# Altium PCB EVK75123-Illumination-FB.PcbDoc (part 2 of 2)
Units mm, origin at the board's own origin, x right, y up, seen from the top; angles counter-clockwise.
Board outline 80 x 50 mm, 4 copper layers (Top Layer, GND, VCC, Bottom Layer), stack 0.99 mm thick; 109 components, 50 nets, 287 pads, 1161 vias.
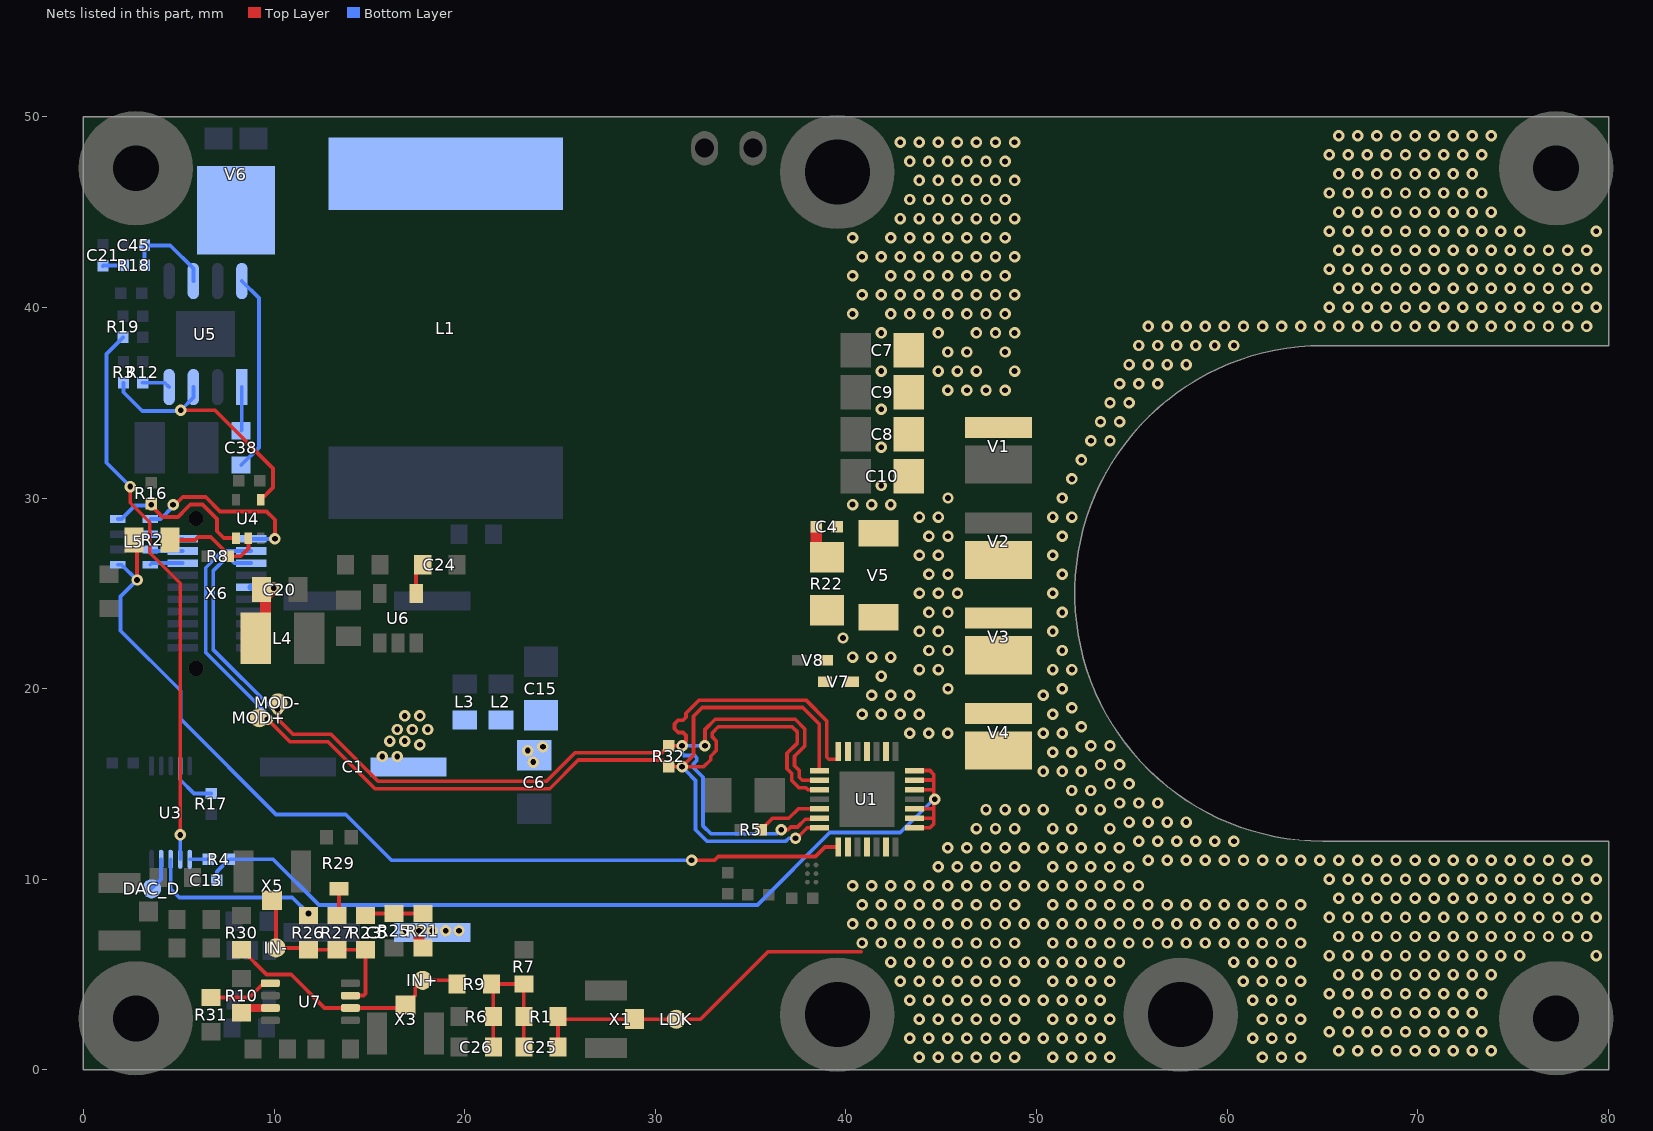
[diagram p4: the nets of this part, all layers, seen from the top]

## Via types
v1: diameter 0.6, hole 0.3, Top Layer to Bottom Layer, tented both sides, 1159 vias
v2: diameter 0.6, hole 0.3, Top Layer to Bottom Layer, 2 vias

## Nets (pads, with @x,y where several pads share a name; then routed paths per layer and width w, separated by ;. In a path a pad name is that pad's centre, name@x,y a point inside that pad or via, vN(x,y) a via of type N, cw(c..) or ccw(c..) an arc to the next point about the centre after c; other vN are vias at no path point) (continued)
LD2: V2.2 V3.1
  other v1: 65.85,1 66.85,1 67.85,1 68.85,1 69.85,1 70.85,1 71.85,1 72.85,1 73.85,1 65.35,2 66.35,2 67.35,2 68.35,2 69.35,2 70.35,2 71.35,2 72.35,2 73.35,2 65.85,3 66.85,3 67.85,3 68.85,3 69.85,3 70.85,3 71.85,3 72.85,3 65.35,4 66.35,4 67.35,4 68.35,4 69.35,4 70.35,4 71.35,4 72.35,4 73.35,4 65.85,5 66.85,5 67.85,5 68.85,5 69.85,5 70.85,5 71.85,5 72.85,5 73.85,5 65.35,6 66.35,6 67.35,6 68.35,6 69.35,6 70.35,6 71.35,6 72.35,6 73.35,6 74.35,6 75.35,6 79.35,6 65.85,7 66.85,7 67.85,7 68.85,7 69.85,7 70.85,7 71.85,7 72.85,7 73.85,7 74.85,7 75.85,7 76.85,7 77.85,7 78.85,7 65.35,8 66.35,8 67.35,8 68.35,8 69.35,8 70.35,8 71.35,8 72.35,8 73.35,8 74.35,8 75.35,8 76.35,8 77.35,8 78.35,8 79.35,8 65.85,9 66.85,9 67.85,9 68.85,9 69.85,9 70.85,9 71.85,9 72.85,9 73.85,9 74.85,9 75.85,9 76.85,9 77.85,9 78.85,9 65.35,10 66.35,10 67.35,10 68.35,10 69.35,10 70.35,10 71.35,10 72.35,10 73.35,10 74.35,10 75.35,10 76.35,10 77.35,10 78.35,10 79.35,10 55.85,11 56.85,11 57.85,11 58.85,11 59.85,11 60.85,11 61.85,11 62.85,11 63.85,11 64.85,11 65.85,11 66.85,11 67.85,11 68.85,11 69.85,11 70.85,11 71.85,11 72.85,11 73.85,11 74.85,11 75.85,11 76.85,11 77.85,11 78.85,11 55.35,12 56.35,12 57.35,12 58.35,12 59.35,12 60.35,12 54.85,13 55.85,13 56.85,13 57.85,13 54.35,14 55.35,14 56.35,14 53.85,15 54.85,15 53.35,16 54.35,16 52.85,17 53.85,17 52.35,18 51.85,19 45.35,20 51.35,20 43.85,21 44.85,21 50.85,21 51.85,21 44.35,22 45.35,22 51.35,22 43.85,23 44.85,23 50.85,23 44.35,24 45.35,24 51.35,24 43.85,25 44.85,25 45.85,25 50.85,25 44.35,26 45.35,26 51.35,26 43.85,27 44.85,27 50.85,27 44.35,28 45.35,28 51.35,28 43.85,29 44.85,29 50.85,29 51.85,29 45.35,30 51.35,30 51.85,31 52.35,32 52.85,33 53.85,33 53.35,34 54.35,34 53.85,35 54.85,35 54.35,36 55.35,36 56.35,36 54.85,37 55.85,37 56.85,37 57.85,37 55.35,38 56.35,38 57.35,38 58.35,38 59.35,38 60.35,38 55.85,39 56.85,39 57.85,39 58.85,39 59.85,39 60.85,39 61.85,39 62.85,39 63.85,39 64.85,39 65.85,39 66.85,39 67.85,39 68.85,39 69.85,39 70.85,39 71.85,39 72.85,39 73.85,39 74.85,39 75.85,39 76.85,39 77.85,39 78.85,39 65.35,40 66.35,40 67.35,40 68.35,40 69.35,40 70.35,40 71.35,40 72.35,40 73.35,40 74.35,40 75.35,40 76.35,40 77.35,40 78.35,40 79.35,40 65.85,41 66.85,41 67.85,41 68.85,41 69.85,41 70.85,41 71.85,41 72.85,41 73.85,41 74.85,41 75.85,41 76.85,41 77.85,41 78.85,41 65.35,42 66.35,42 67.35,42 68.35,42 69.35,42 70.35,42 71.35,42 72.35,42 73.35,42 74.35,42 75.35,42 76.35,42 77.35,42 78.35,42 79.35,42 65.85,43 66.85,43 67.85,43 68.85,43 69.85,43 70.85,43 71.85,43 72.85,43 73.85,43 74.85,43 75.85,43 76.85,43 77.85,43 78.85,43 65.35,44 66.35,44 67.35,44 68.35,44 69.35,44 70.35,44 71.35,44 72.35,44 73.35,44 74.35,44 75.35,44 79.35,44 65.85,45 66.85,45 67.85,45 68.85,45 69.85,45 70.85,45 71.85,45 72.85,45 73.85,45 65.35,46 66.35,46 67.35,46 68.35,46 69.35,46 70.35,46 71.35,46 72.35,46 73.35,46 65.85,47 66.85,47 67.85,47 68.85,47 69.85,47 70.85,47 71.85,47 72.85,47 65.35,48 66.35,48 67.35,48 68.35,48 69.35,48 70.35,48 71.35,48 72.35,48 73.35,48 65.85,49 66.85,49 67.85,49 68.85,49 69.85,49 70.85,49 71.85,49 72.85,49 73.85,49
LD3: V3.2 V4.1
  other v1: 50.843,0.658 51.843,0.658 52.843,0.658 53.843,0.658 61.843,0.658 62.843,0.658 63.843,0.658 50.343,1.658 51.343,1.658 52.343,1.658 53.343,1.658 61.343,1.658 62.343,1.658 63.343,1.658 50.843,2.658 51.843,2.658 52.843,2.658 53.843,2.658 61.843,2.658 62.843,2.658 63.843,2.658 50.343,3.658 51.343,3.658 52.343,3.658 53.343,3.658 61.343,3.658 62.343,3.658 63.343,3.658 50.843,4.658 51.843,4.658 52.843,4.658 53.843,4.658 60.843,4.658 61.843,4.658 62.843,4.658 63.843,4.658 50.343,5.658 51.343,5.658 52.343,5.658 53.343,5.658 54.343,5.658 60.343,5.658 61.343,5.658 62.343,5.658 63.343,5.658 50.843,6.658 51.843,6.658 52.843,6.658 53.843,6.658 54.843,6.658 55.843,6.658 56.843,6.658 57.843,6.658 58.843,6.658 59.843,6.658 60.843,6.658 61.843,6.658 62.843,6.658 63.843,6.658 50.343,7.658 51.343,7.658 52.343,7.658 53.343,7.658 54.343,7.658 55.343,7.658 56.343,7.658 57.343,7.658 58.343,7.658 59.343,7.658 60.343,7.658 61.343,7.658 62.343,7.658 63.343,7.658 50.843,8.658 51.843,8.658 52.843,8.658 53.843,8.658 54.843,8.658 55.843,8.658 56.843,8.658 57.843,8.658 58.843,8.658 59.843,8.658 60.843,8.658 61.843,8.658 62.843,8.658 63.843,8.658 50.343,9.658 51.343,9.658 52.343,9.658 53.343,9.658 54.343,9.658 55.343,9.658 50.843,10.658 51.843,10.658 52.843,10.658 53.843,10.658 54.843,10.658 50.343,11.658 51.343,11.658 52.343,11.658 53.343,11.658 54.343,11.658 50.843,12.658 51.843,12.658 53.843,12.658 50.343,13.658 52.343,13.658 53.343,13.658 51.843,14.658 52.843,14.658 50.343,15.658 51.343,15.658 52.343,15.658 50.843,16.658 51.843,16.658 50.343,17.658 51.343,17.658 50.843,18.658 50.343,19.658
LDEN: L5.4 R16.1 U4.1 | length 8.2
  Top Layer w0.2: v1(3.55,29.65) 3.55,29.6 4.15,29 4.95,29 5.17,29.22 5.17,29.227 5.598,29.655 6.245,29.655 7,28.9 7,28.259 7.359,27.9 U4.1@8,27.9
  Bottom Layer w0.2: L5.4@1.8,28.9 2,28.9 2.7,29.6 3.55,29.6 v1(3.55,29.65)
LDK: C25.1 LDK.1 R1.1 R22.1 U1.9 U1.11 U1.13 U1.23 U1.25 U1.27 V4.2 V5.1 V7.2 X1.2 | length 19
  Top Layer w0.2: C25.1@24.9,1.2 R1.1@24.9,2.8 25.041,2.659 X1.2@28.9,2.659 LDK.1@31.1,2.659 32.359,2.659 35.9,6.2 40.8,6.2
  other v1: 43.843,0.658 44.843,0.658 45.843,0.658 46.843,0.658 47.843,0.658 48.843,0.658 43.343,1.658 44.343,1.658 45.343,1.658 46.343,1.658 47.343,1.658 48.343,1.658 49.343,1.658 43.843,2.658 44.843,2.658 45.843,2.658 46.843,2.658 47.843,2.658 48.843,2.658 43.343,3.658 44.343,3.658 45.343,3.658 46.343,3.658 47.343,3.658 48.343,3.658 49.343,3.658 42.843,4.658 43.843,4.658 44.843,4.658 45.843,4.658 46.843,4.658 47.843,4.658 48.843,4.658 42.343,5.658 43.343,5.658 44.343,5.658 45.343,5.658 46.343,5.658 47.343,5.658 48.343,5.658 49.343,5.658 40.843,6.658 41.843,6.658 42.843,6.658 43.843,6.658 44.843,6.658 45.843,6.658 46.843,6.658 47.843,6.658 48.843,6.658 40.343,7.658 41.343,7.658 42.343,7.658 43.343,7.658 44.343,7.658 45.343,7.658 46.343,7.658 47.343,7.658 48.343,7.658 49.343,7.658 40.843,8.658 41.843,8.658 42.843,8.658 43.843,8.658 44.843,8.658 45.843,8.658 46.843,8.658 47.843,8.658 48.843,8.658 40.343,9.658 41.343,9.658 42.343,9.658 43.343,9.658 44.343,9.658 45.343,9.658 46.343,9.658 47.343,9.658 48.343,9.658 49.343,9.658 44.843,10.658 45.843,10.658 46.843,10.658 47.843,10.658 48.843,10.658 45.343,11.658 46.343,11.658 47.343,11.658 48.343,11.658 49.343,11.658 46.843,12.658 47.843,12.658 48.843,12.658 47.343,13.658 48.343,13.658 49.343,13.658 43.343,17.658 44.343,17.658 45.343,17.658 40.843,18.658 41.843,18.658 42.843,18.658 43.843,18.658 41.343,19.658 42.343,19.658 43.343,19.658 41.843,20.658 40.343,21.658 41.343,21.658 42.343,21.658 39.843,22.658
MOD_N: MOD-.1 R32.1 U1.14 U1.16 U1.20 X6.15 | length 71.9
  Top Layer w0.192: v1(10.18,18.93) 10.18,18.642 10.196,18.626 10.196,18.408 10.994,17.61 12.99,17.61 15.455,15.145 24.291,15.145 25.792,16.646 30.346,16.646 R32.1@30.7,17 v1(31.4,17) 31.608,17.208 31.608,17.542 31.45,17.7 31.2,17.7 31,17.9 31,18.15 31.2,18.35 31.458,18.35 31.608,18.5 31.608,18.708 32.3,19.4 37.9,19.4 38.992,18.308 38.992,16.408 39.1,16.3 39.6,16.3 U1.14@39.6,16.7 ; v1@32.6,17.205 32.6,17.854 33.138,18.392 37.333,18.392 37.842,17.883 37.842,16.992 37.3,16.45 37.3,15.962 37.55,15.712 37.55,15.35 37.7,15.2 38.004,15.2 U1.16@38.6,15.2 ; v1(36.6,12.6) 36.957,12.6 37.103,12.746 37.46,12.746 37.86,13.146 38.196,13.146 38.25,13.2 U1.20@38.6,13.2
  Bottom Layer w0.192: X6.15@8.8,26.588 7.904,26.588 7.661,26.831 7.457,26.831 6.8,26.174 6.8,22.057 9.927,18.93 v1(10.18,18.93) ; v1(32.6,17) v1(31.4,17) 31.4,16.6 31.504,16.496 32.054,16.496 32.175,16.375 32.175,16.225 32,16.05 32,15.85 32.5,15.35 32.5,12.8 32.904,12.396 36.396,12.396 v1(36.6,12.6)
MOD_P: MOD+.1 R32.2 U1.15 U1.17 U1.21 X6.17 | length 71.8
  Top Layer w0.192: v1(9.65,18.4) 10.831,17.218 12.827,17.218 15.292,14.753 24.453,14.753 25.954,16.254 30.346,16.254 R32.2@30.7,15.9 v1(31.4,15.9) ; v1@37.246,11.978 37.968,12.7 U1.21@38.6,12.7 ; U1.17@38.6,14.7 38.004,14.7 37.896,14.808 37.538,14.808 37.158,15.188 37.158,15.55 36.908,15.8 36.908,16.612 37.45,17.154 37.45,17.721 37.171,18 33.3,18 32.992,17.692 32.992,17.458 33.2,17.25 33.2,16.75 32.9,16.45 32.9,16.275 32.525,15.9 v1(31.4,15.9) ; U1.15@38.6,15.7 38.6,18.146 37.738,19.008 32.462,19.008 32,18.546 32,16.5 v1(31.4,15.9)
  Bottom Layer w0.192: X6.17@8.8,27.223 7.294,27.223 6.408,26.336 6.408,21.895 9.65,18.653 v1(9.65,18.4) ; v1(31.4,15.9) 31.608,15.692 31.608,15.688 32.108,15.188 32.108,12.592 32.696,12.004 36.847,12.004 36.993,12.15 v1(37.35,12.15)
NERR: L5.1 R2.1 U1.22 | length 50.4
  Top Layer w0.2: R2.1@2.65,27.8 2.51,27.66 2.81,27.359 v1(2.81,25.7) ; v1(31.9,11) 33.1,11 33.3,11.2 38.4,11.2 38.9,11.7 U1.22@39.6,11.7
  Bottom Layer w0.2: L5.1@1.8,26.5 2,26.5 2.8,25.7 v1(2.81,25.7) 1.95,24.84 1.95,23.04 5.1,19.89 5.1,18.4 10.1,13.4 13.756,13.4 16.156,11 20.9,11 v1(31.9,11)
NERRR: R2.2 R8.1 U4.2 | length 5.3
  Top Layer w0.2: R2.2@4.55,27.8 5.85,27.8 6,27.95 6.678,27.95 7.6,27.028 R8.1@7.6,26.95 8.25,26.95 8.65,27.35 U4.2@8.65,27.9
NetC4_1: C4.1 R22.2 | length 1.1
  Top Layer w0.6: R22.2@38.45,27.45 C4.1@38.45,28.5
NetC13_2: C13.2 R4.1 U1.1 U1.2 U1.3 U1.5 U1.6 U1.7 | length 50.4
  Top Layer w0.2: U1.1@43.6,12.7 44.4,12.7 44.6,12.9 44.6,13.2 ; U1.2@43.6,13.2 44.6,13.2 ; U1.3@43.6,13.7 44.6,13.7 ; U1.5@43.6,14.7 44.6,14.7 ; U1.6@43.6,15.2 44.6,15.2 ; U1.7@43.6,15.7 44.4,15.7 44.6,15.5 44.6,15.2 ; 44.6,13.2 44.6,13.7 ; 44.6,13.7 44.6,14.2 44.6,14.7 ; 44.6,14.7 44.6,15.2
  Bottom Layer w0.2: C13.2@7,9.95 7,10.4 R4.1@7.65,11.05 9.95,11.05 12.35,8.65 35.35,8.65 39.15,12.45 ; 39.15,12.45 42.85,12.45 v1@44.6,14.2
  other v1: 44.65,14.2
NetC20_2: C20.2 L4.1 X6.11 | length 4.2
  Top Layer w0.6: L4.1@9.05,22.65 9.05,23.25 9.55,23.75 C20.2@9.55,24.885 ; C20.2@9.55,24.835 v1(9.982,25.268)
  Bottom Layer w0.4: X6.11@8.8,25.318 v1@9.982,25.318
NetC21_2: C21.2 R18.2 | length 1.1
  Bottom Layer w0.2: C21.2@1.025,42.175 1.05,42.2 R18.2@2.1,42.2
NetC24_1: C24.1 U6.4 | length 1.6
  Top Layer w0.2: U6.4@17.45,25 17.45,26.15 C24.1@17.8,26.5
NetC25_2: C25.2 C26.1 R1.2 R6.1 R7.2 R9.1 | length 8.3
  Top Layer w0.2: R9.1@21.4,4.5 R9.1@21.5,4.4 ; C26.1@21.5,1.2 R6.1@21.5,2.8 R9.1@21.5,4.4 ; C25.2@23.1,1.2 R1.2@23.1,2.8 R7.2@23.1,4.5 21.6,4.5 R9.1@21.5,4.4
NetC38_2: C38.2 U5.1 | length 2.3
  Bottom Layer w0.2: C38.2@8.275,33.525 8.305,33.555 U5.1@8.305,35.82
NetC45_2: C45.2 R18.1 U5.6 | length 4.8
  Bottom Layer w0.2: R18.1@3.2,42.2 C45.2@3.2,43.25 4.55,43.25 5.765,42.035 U5.6@5.765,41.38
NetIN+_1: IN+.1 R9.2 R30.1 U7.2 X3.2 | length 13.5
  Top Layer w0.2: R30.1@8.3,6.3 9.6,5 10.9,5 12.65,3.25 U7.2@14,3.25 16.75,3.25 X3.2@16.9,3.4 17.4,3.9 17.4,4.3 IN+.1@17.8,4.7 19.4,4.7 R9.2@19.6,4.5
NetIN-_1: IN-.1 R23.2 R26.2 R27.2 U7.3 X5.2 | length 10.5
  Top Layer w0.2: X5.2@9.9,8.9 10.1,8.7 IN-.1@10.1,6.4 11.7,6.4 R26.2@11.8,6.3 R27.2@13.3,6.3 R23.2@14.8,6.3 14.8,4 14.7,3.9 U7.3@14,3.9
NetL5_5: L5.5 X6.19 | length 9.8
  Top Layer w0.2: v1(4.7,29.65) 4.8,29.65 5.205,30.055 6.411,30.055 7.166,29.3 9.6,29.3 10.042,28.858 v1(10.042,27.858)
  Bottom Layer w0.2: L5.5@3.5,28.9 4.05,28.9 4.7,29.55 v1(4.7,29.65) ; X6.19@8.8,27.858 v1(10.042,27.858)
NetL5_6: L5.6 X6.20 | length 1.8
  Bottom Layer w0.2: L5.6@3.5,28.1 4.05,28.1 4.292,27.858 X6.20@5.2,27.858
NetL5_7: L5.7 X6.18 | length 1.7
  Bottom Layer w0.2: L5.7@3.5,27.3 3.578,27.223 X6.18@5.2,27.223
NetL5_8: L5.8 X6.16 | length 1.7
  Bottom Layer w0.2: L5.8@3.5,26.5 3.588,26.588 X6.16@5.2,26.588
NetR5_1: R5.1 U1.19 | length 3.5
  Top Layer w0.2: R5.1@35.55,12.6 36.15,13.2 37,13.2 37.5,13.7 U1.19@38.6,13.7
NetR10_1: R10.1 U7.7 | length 1.6
  Top Layer w0.4: R10.1@8.3,2.9 8.65,3.25 U7.7@9.8,3.25
NetR17_2: R17.2 U3.4 | length 2.7
  Bottom Layer w0.2: U3.4@5.075,15.95 5.075,15.225 5.8,14.5 R17.2@6.7,14.5
NetR21_2: R21.2 R23.1 R25.1 | length 3
  Top Layer w0.2: R23.1@14.8,8.1 14.9,8.2 R21.2@17.8,8.2
NetR27_1: R27.1 R29.2 | length 1.4
  Top Layer w0.2: R27.1@13.3,8.1 13.4,8.2 R29.2@13.4,9.5
NetR31_2: R31.2 U7.5 | length 3.4
  Top Layer w0.2: R31.2@6.7,3.8 8.7,3.8 9.45,4.55 U7.5@9.8,4.55
NetV7_1: V7.1 V8.2
PEN: R3.2 U4.4 U5.3 | length 13.4
  Top Layer w0.2: v1(5.1,34.6) 6.9,34.6 9.95,31.55 9.95,30.55 U4.4@9.3,29.9
  Bottom Layer w0.2: R3.2@2.1,36.05 2.1,35.55 3.08,34.57 5.07,34.57 v1(5.1,34.6) 5.765,35.265 U5.3@5.765,35.82
RT17V: R12.1 U5.4 | length 1.5
  Bottom Layer w0.2: R12.1@3.1,36.05 4.265,36.05 U5.4@4.495,35.82
SW17V: C38.1 L1.1 U5.8 V6.2 | length 10.4
  Bottom Layer w0.2: C38.1@8.275,31.725 9.2,32.65 9.2,40.485 U5.8@8.305,41.38
V_CI: R4.2 U3.6 | length 1
  Bottom Layer w0.2: U3.6@5.575,11.05 R4.2@6.55,11.05
V_DAC_C: R26.1 U3.8 | length 9.4
  Top Layer w0.2: R26.1@11.8,8.1 v1(11.8,8.2)
  Bottom Layer w0.2: U3.8@4.575,11.05 4.575,9.5 5.025,9.05 10.95,9.05 v1(11.8,8.2)
V_DAC_D: DAC_D.1 U3.9 | length 1.8
  Bottom Layer w0.2: DAC_D.1@3.575,9.5 4.075,10 U3.9@4.075,11.05
VLD: C1.1 C4.2 C5.1 C6.1 C7.2 C8.2 C9.2 C10.2 C15.2 L2.2 L3.2 R21.1 V1.1 V5.2 | length 1
  Top Layer w0.6: v1(17.6,7.3) 17.6,6.6 R21.1@17.8,6.4
  other v1: 16.9,7.3 18.3,7.3 19,7.3 19.7,7.3 23.6,16.15 15.669,16.441 16.456,16.441 23.3,16.75 24.1,16.95 17.65,17.055 16.063,17.25 16.85,17.25 16.456,17.859 17.256,17.859 18.056,17.859 16.85,18.567 17.65,18.567 40.343,29.658 41.343,29.658 42.343,29.658 41.843,30.658 41.843,32.658 41.843,34.658 45.343,35.658 46.343,35.658 47.343,35.658 48.343,35.658 41.843,36.658 44.843,36.658 45.843,36.658 46.843,36.658 48.843,36.658 45.343,37.658 46.343,37.658 48.343,37.658 41.843,38.658 44.843,38.658 46.843,38.658 47.843,38.658 48.843,38.658 40.343,39.658 42.343,39.658 43.343,39.658 44.343,39.658 45.343,39.658 46.343,39.658 47.343,39.658 48.343,39.658 40.843,40.658 41.843,40.658 42.843,40.658 43.843,40.658 44.843,40.658 45.843,40.658 46.843,40.658 47.843,40.658 48.843,40.658 40.343,41.658 42.343,41.658 43.343,41.658 44.343,41.658 45.343,41.658 46.343,41.658 47.343,41.658 48.343,41.658 40.843,42.658 41.843,42.658 42.843,42.658 43.843,42.658 44.843,42.658 45.843,42.658 46.843,42.658 47.843,42.658 48.843,42.658 40.343,43.658 42.343,43.658 43.343,43.658 44.343,43.658 45.343,43.658 46.343,43.658 47.343,43.658 48.343,43.658 42.843,44.658 43.843,44.658 44.843,44.658 45.843,44.658 46.843,44.658 47.843,44.658 48.843,44.658 43.343,45.658 44.343,45.658 45.343,45.658 46.343,45.658 47.343,45.658 48.343,45.658 43.843,46.658 44.843,46.658 45.843,46.658 46.843,46.658 47.843,46.658 48.843,46.658 43.343,47.658 44.343,47.658 45.343,47.658 46.343,47.658 47.343,47.658 48.343,47.658 42.843,48.658 43.843,48.658 44.843,48.658 45.843,48.658 46.843,48.658 47.843,48.658 48.843,48.658
VPROG: R19.2 U3.7 | length 29.3
  Top Layer w0.2: v2(2.45,30.6) 2.45,29.75 3.475,28.725 3.475,27.125 5.075,25.525 v1(5.075,12.325)
  Bottom Layer w0.2: R19.2@2.075,38.425 1.2,37.55 1.2,31.85 v2(2.45,30.6) ; U3.7@5.075,11.05 v1(5.075,12.325)
pads on no net: P1.1 P2.1 P3.1 P4.1 P5.1 P6.1 PCB.1 U2.C1 U3.5 U7.4 U8.4 X6.A1 X6.A2

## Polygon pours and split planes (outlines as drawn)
GND on Top Layer "GND" (solid, remove dead copper, pour order 28): 0,0 0,50 42.7,50 42.7,0
VLD on Top Layer "LDK" (solid, remove dead copper, pour order 6): 39.9,34.9 39.9,36.8 39.9,50 49.75,50 49.75,34.65 49.75,32.25 46,32.25 42.8,29.05 42.8,25.3 38.1,25.3 38.1,28.25 39.9,30.05
LD2 on Top Layer "LD2" (solid, remove dead copper, pour order 12): 42.8,34.05 64.6,50 80,50 80,0 64.6,0 42.8,17.75
LD1 on Top Layer "LD3" (solid, remove dead copper, pour order 10): 46.25,27.25 46.25,50 64.343,50 64.343,40.5 55.847,40.5 49.216,27.25
LD3 on Top Layer "LD3" (solid, remove dead copper, pour order 8): 46.25,22.75 46.25,0 64.343,0 64.343,9.5 55.847,9.5 49.216,22.75
LDK on Top Layer "LDK" (solid, remove dead copper, pour order 0): 39.9,15.1 39.9,13.2 39.9,0 49.75,0 49.75,15.35 49.75,17.75 46,17.75 42.8,20.95 42.8,24.7 38.1,24.7 38.1,23.1 39.9,21.3 39.9,20.7
GND on Bottom Layer "GND" (solid, remove dead copper, pour order 26): 0,0 0,50 44.65,50 44.65,0
LD2 on Bottom Layer "LD2" (solid, remove dead copper, pour order 22): 42.8,34.05 64.55,50 80,50 80,0 64.55,0 42.8,17.938
LD1 on Bottom Layer "LD1" (solid, remove dead copper, pour order 20): 46.25,28 46.25,50 64.35,50 64.35,40.5 55.75,40.5 49.6,28
LD3 on Bottom Layer "LD3" (solid, remove dead copper, pour order 18): 46.25,22.8 46.25,0 64.344,0 64.344,9.5 55.843,9.5 49.75,21.658 49.75,22.8
LDK on Bottom Layer "LDK" (solid, remove dead copper, pour order 14): 42.8,15.85 44.5,14.15 42.8,12.5 39.9,12.5 39.9,0 49.75,0 49.75,15.75 49.75,17.75 46,17.75 42.8,20.95 42.8,24.7 38.1,24.7 38.1,23.1 39.9,21.3 39.9,15.85
VLD on Bottom Layer "VLD" (solid, remove dead copper, pour order 16): 39.2,28 39.2,29.5 39.7,30 39.7,50 49.75,50 49.75,34.35 49.75,33.15 46.05,33.15 46,33.1 42.8,29.9 42.8,27.4 39.2,27.4
VLD on Bottom Layer "VLD" (solid, remove dead copper, pour order 24): 24.9,19.4 17.25,19.4 15.05,17.2 15.05,15.4 18.8,15.4 20.4,17 21.429,17 21.452,16.977 22.729,15.7 23.95,15.7 24.9,15.7
GND on GND (split plane): 39.348,40.35 39.356,40.285 39.382,40.224 39.422,40.172 44.113,35.48 44.166,35.44 44.226,35.415 44.292,35.406 49.648,35.406 49.648,15.352 46.9,15.352 46.835,15.344 46.774,15.318 46.744,15.296 46.722,15.278 45.722,14.278 45.682,14.226 45.656,14.165 45.648,14.1 45.648,13.504 43.196,11.052 40.4,11.052 40.335,11.044 40.274,11.018 40.222,10.978 39.122,9.878 39.082,9.826 39.056,9.765 39.048,9.7 39.048,2.9 39.056,2.835 39.082,2.774 39.122,2.722 39.174,2.682 39.235,2.656 39.3,2.648 39.365,2.656 40.6,1.422 40.652,1.382 40.713,1.356 40.778,1.348 54.1,1.348 54.165,1.356 54.226,1.382 54.278,1.422 55.078,2.222 55.118,2.274 55.144,2.335 55.152,2.4 55.152,3.796 56.354,4.998 58.246,4.998 61.822,1.422 61.874,1.382 61.935,1.356 62,1.348 64.198,1.348 64.198,0.202 0.202,0.202 0.202,49.798 39.348,49.798
LDK on GND (split plane): 49.648,1.852 40.883,1.852 39.722,3.013 39.67,3.053 39.609,3.078 39.552,3.086 39.552,9.596 40.504,10.548 43.3,10.548 43.365,10.556 43.426,10.582 43.478,10.622 46.078,13.222 46.118,13.274 46.144,13.335 46.152,13.4 46.152,13.996 47.004,14.848 49.648,14.848
VLD on GND (split plane): 49.648,35.91 44.396,35.91 39.852,40.454 39.852,49.798 49.648,49.798
LD2 on GND (split plane): 79.798,38.202 65,38.202 64.506,38.193 64.013,38.165 63.522,38.119 63.032,38.055 62.546,37.972 62.062,37.871 61.583,37.752 61.109,37.616 60.64,37.461 60.177,37.29 59.721,37.101 59.272,36.895 58.831,36.672 58.399,36.434 57.976,36.179 57.563,35.908 57.16,35.623 56.768,35.322 56.388,35.007 56.02,34.678 55.665,34.335 55.322,33.98 54.993,33.612 54.678,33.232 54.377,32.84 54.092,32.437 53.821,32.024 53.566,31.601 53.328,31.169 53.105,30.728 52.899,30.279 52.71,29.823 52.539,29.36 52.384,28.891 52.248,28.417 52.129,27.938 52.028,27.454 51.945,26.968 51.881,26.478 51.835,25.987 51.807,25.494 51.798,25 51.807,24.506 51.835,24.013 51.881,23.522 51.945,23.032 52.028,22.546 52.129,22.062 52.248,21.583 52.384,21.109 52.539,20.64 52.71,20.177 52.899,19.721 53.105,19.272 53.328,18.831 53.566,18.399 53.821,17.976 54.092,17.563 54.377,17.16 54.678,16.768 54.993,16.388 55.322,16.02 55.665,15.665 56.02,15.322 56.388,14.993 56.768,14.678 57.16,14.377 57.563,14.092 57.976,13.821 58.399,13.566 58.831,13.328 59.272,13.105 59.721,12.899 60.177,12.71 60.64,12.539 61.109,12.384 61.583,12.248 62.062,12.129 62.546,12.028 63.032,11.945 63.522,11.881 64.013,11.835 64.506,11.807 65,11.798 79.798,11.798 79.798,0.202 64.702,0.202 64.702,9.45 64.694,9.515 64.676,9.558 64.668,9.576 64.651,9.599 64.628,9.628 64.428,9.828 64.376,9.868 64.315,9.894 64.25,9.902 55.957,9.902 50.152,21.659 50.152,28.341 55.957,40.098 64.25,40.098 64.315,40.106 64.376,40.132 64.428,40.172 64.628,40.372 64.651,40.401 64.668,40.424 64.676,40.442 64.694,40.485 64.702,40.55 64.702,49.798 79.798,49.798
LD1 on GND (split plane): 64.198,40.654 64.146,40.602 55.8,40.602 55.792,40.601 55.784,40.602 55.759,40.597 55.735,40.594 55.727,40.59 55.719,40.589 55.697,40.578 55.674,40.568 55.667,40.563 55.66,40.56 55.641,40.543 55.622,40.528 55.617,40.522 55.61,40.516 55.597,40.496 55.582,40.476 55.578,40.468 55.574,40.462 50.152,29.48 50.152,35.658 50.152,49.798 64.198,49.798
LD3 on GND (split plane): 55.447,9.796 55.432,9.776 55.406,9.715 55.398,9.65 55.406,9.585 55.432,9.524 55.472,9.472 55.524,9.432 55.585,9.406 55.65,9.398 64.146,9.398 64.198,9.346 64.198,1.852 62.104,1.852 58.528,5.428 58.476,5.468 58.415,5.494 58.35,5.502 56.25,5.502 56.185,5.494 56.124,5.468 56.094,5.446 56.072,5.428 54.722,4.078 54.682,4.026 54.656,3.965 54.648,3.9 54.648,2.504 53.996,1.852 50.152,1.852 50.152,15.1 50.152,20.52
3V3 on VCC (split plane): 19.248,32.546 19.248,22.504 14.922,18.178 14.882,18.126 14.856,18.065 14.848,18 14.848,15.5 14.856,15.435 14.882,15.374 14.922,15.322 15.848,14.396 15.848,7 15.856,6.935 15.882,6.874 15.922,6.822 16.322,6.422 16.344,6.404 16.374,6.382 16.435,6.356 16.5,6.348 20,6.348 20.065,6.356 20.126,6.382 20.178,6.422 21.6,7.843 21.617,7.866 21.64,7.896 21.665,7.956 21.674,8.022 21.674,12.217 24.904,15.448 32.148,15.448 32.148,12.8 32.156,12.735 32.182,12.674 32.222,12.622 35.248,9.596 35.248,9.004 34.796,8.552 24.1,8.552 24.035,8.544 23.974,8.518 23.922,8.478 20.296,4.852 15.304,4.852 13.552,6.604 13.552,13.1 13.544,13.165 13.526,13.208 13.518,13.226 13.501,13.249 13.478,13.278 12.952,13.804 12.952,19.896 15.278,22.222 15.318,22.274 15.344,22.335 15.352,22.4 15.352,22.9 15.344,22.965 15.326,23.008 15.318,23.026 15.301,23.049 15.278,23.078 14.578,23.778 14.526,23.818 14.465,23.844 14.4,23.852 9.404,23.852 6.152,27.104 6.152,28.821 7.678,30.347 7.718,30.399 7.744,30.46 7.752,30.525 7.752,33.448 18.346,33.448
5V0 on VCC (split plane): 29.948,43.454 19.5,33.007 18.628,33.878 18.576,33.918 18.515,33.944 18.45,33.952 7.726,33.952 7.718,33.969 7.678,34.022 7.022,34.678 6.969,34.718 6.909,34.744 6.843,34.752 5.3,34.752 5.235,34.744 5.174,34.718 5.122,34.678 4.422,33.978 4.382,33.926 4.356,33.865 4.348,33.8 4.348,32.404 3.022,31.078 2.982,31.026 2.956,30.965 2.948,30.9 2.948,26.8 2.956,26.735 2.982,26.674 3.022,26.622 5.648,23.996 5.648,20.975 5.656,20.91 5.682,20.849 5.722,20.797 6.397,20.122 6.419,20.104 6.449,20.082 6.51,20.056 6.575,20.048 8.2,20.048 8.265,20.056 8.326,20.082 8.378,20.122 9.478,21.222 9.518,21.274 9.544,21.335 9.552,21.4 9.552,23.348 14.296,23.348 14.848,22.796 14.848,22.504 12.522,20.178 12.482,20.126 12.456,20.065 12.448,20 12.448,13.7 12.456,13.635 12.482,13.574 12.522,13.522 13.048,12.996 13.048,6.5 13.056,6.435 13.082,6.374 13.122,6.322 15.022,4.422 15.074,4.382 15.135,4.356 15.2,4.348 20.4,4.348 20.465,4.356 20.526,4.382 20.578,4.422 24.204,8.048 34.9,8.048 34.965,8.056 35.026,8.082 35.078,8.122 35.678,8.722 35.701,8.751 35.718,8.774 35.726,8.792 35.744,8.835 35.752,8.9 35.752,9.7 35.744,9.765 35.718,9.826 35.678,9.878 32.652,12.904 32.652,15.448 36.7,15.448 36.74,15.453 37.298,14.896 37.298,10.9 37.306,10.835 37.332,10.774 37.372,10.722 38.998,9.096 38.998,0.301 0.301,0.301 0.301,49.699 29.948,49.699
24V on VCC (split plane): 7.248,33.739 7.248,30.629 5.722,29.103 5.682,29.051 5.656,28.99 5.648,28.925 5.648,27 5.656,26.935 5.682,26.874 5.722,26.822 9.048,23.496 9.048,21.504 8.096,20.552 6.679,20.552 6.152,21.079 6.152,24.1 6.144,24.165 6.118,24.226 6.078,24.278 3.452,26.904 3.452,30.796 4.778,32.122 4.818,32.174 4.844,32.235 4.852,32.3 4.852,33.696 5.404,34.248 6.739,34.248
VLD on VCC (split plane): 49.749,34.4 49.749,33.163 49.637,33.051 46.3,33.051 46.261,33.046 46.224,33.031 46.193,33.007 46.043,32.857 46.019,32.826 46.004,32.789 45.999,32.75 45.999,30.713 41.468,26.182 36.593,21.307 36.569,21.276 36.554,21.239 36.549,21.2 36.549,16.049 36.522,16.028 36.482,15.976 36.472,15.952 24.8,15.952 24.735,15.944 24.674,15.918 24.622,15.878 21.243,12.5 21.203,12.448 21.178,12.387 21.17,12.322 21.17,8.126 19.896,6.852 16.604,6.852 16.352,7.104 16.352,14.5 16.344,14.565 16.318,14.626 16.296,14.656 16.278,14.678 15.352,15.604 15.352,17.896 19.678,22.222 19.718,22.274 19.744,22.335 19.752,22.4 19.752,32.546 30.378,43.172 30.418,43.224 30.444,43.285 30.452,43.35 30.452,49.699 49.749,49.699
LDK on VCC (split plane): 42.749,24.687 42.749,21 42.754,20.961 42.769,20.924 42.793,20.893 45.893,17.793 45.924,17.769 45.935,17.765 45.961,17.754 46,17.749 49.649,17.749 49.649,0.301 39.502,0.301 39.502,9.2 39.494,9.265 39.468,9.326 39.428,9.378 37.802,11.004 37.802,15 37.794,15.065 37.768,15.126 37.728,15.178 36.878,16.028 36.851,16.049 36.851,21.137 41.575,25.861
LD2 on VCC (split plane): 189 vertices, not listed, extent 41.789,0.301 79.699,49.699
LD3 on VCC (split plane): 42.649,15.587 42.649,12.813 42.487,12.651 39.713,12.651 39.551,12.813 39.551,15.587 39.713,15.749 42.487,15.749
LD3 on VCC (split plane): 55.715,9.591 55.717,9.587 55.719,9.583 55.728,9.571 55.737,9.558 55.74,9.555 55.743,9.551 55.755,9.542 55.766,9.532 55.771,9.53 55.774,9.527 55.788,9.521 55.802,9.515 55.807,9.514 55.811,9.512 55.826,9.51 55.841,9.507 55.845,9.508 55.85,9.507 64.128,9.507 64.299,9.336 64.299,0.301 49.951,0.301 49.951,17.9 49.951,21.163
LD1 on VCC (split plane): 64.299,40.813 63.987,40.501 55.8,40.501 55.795,40.501 55.79,40.501 55.776,40.498 55.761,40.496 55.756,40.494 55.751,40.493 55.738,40.487 55.724,40.481 55.72,40.478 55.716,40.476 55.705,40.466 55.693,40.457 55.69,40.453 55.686,40.45 55.678,40.437 55.669,40.426 55.667,40.421 55.664,40.417 50.051,29.048 50.051,49.699 64.299,49.699

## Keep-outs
Keep-Out Layer:
  lines w0.2: 0,4.8 0,45.4 ; 4.8,0 37.7,0 ; 4.8,50 37.7,50 ; 41.35,0 55.7,0 ; 41.35,50 59.5,50 75.15,50 ; 59.5,0 75.15,0 ; 80,4.85 80,12 65,12 cw(c65,25) 65,38 80,38 80,45.15

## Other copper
Top Layer:
  rectangle net GND: 54.55,0.3 60.55,2.9
  rectangle: 36.55,0.3 42.55,2.9
  rectangle net NetC25_2: 21,0.7 23.5,5
  region net NetV7_1: 39.3,21.75 38.55,21.75 38.55,20.1 39.3,20.1
  pour cut-out: 37.7,11.2 37.65,11.15 37.65,9.725 37.825,9.55 38.65,9.55 38.75,9.65 38.75,11 38.55,11.2
  pour cut-out: 38.6,16.7 43.6,16.7 43.6,11.7 38.6,11.7
Bottom Layer:
  rectangle net GND: 54.55,0.3 60.55,2.9
  rectangle: 36.55,0.3 42.55,2.9
  region net GND: 6,24.9 3.85,24.9 3.55,24.6 3.55,22.25 3.85,21.95 6,21.95
  region net 24V: 9.6,24.9 7.45,24.9 7.15,24.6 7.15,22.25 7.45,21.95 9.6,21.95
  region net SW17V: 7.8,40.4 7.8,45.4 11.3,48.9 15.5,48.9 15.5,45.4 10.5,40.4
  region net 17V: 20.4,29.4 20.4,25.9 22.6,23.7 22.6,19.7 18.15,19.7 16.3,21.55 16.3,29.4
GND (plane layer: these items are gaps in the copper):
  lines w0.5: 39.3,2.9 39.3,9.7 40.4,10.8 43.3,10.8 45.9,13.4 45.9,14.1 46.9,15.1 49.9,15.1 ; 39.544,2.835 40.778,1.6 54.1,1.6 54.9,2.4 54.9,3.9 56.25,5.25 58.35,5.25 62,1.6 64.45,1.6 ; 39.6,50 39.6,40.35 44.292,35.658 49.9,35.658 ; 49.9,1.658 49.9,35.658 ; 49.9,21.6 55.8,9.65 ; 49.9,28.4 55.8,40.35 64.25,40.35 64.45,40.55 64.45,50 ; 49.9,50 49.9,35.658 ; 55.65,9.65 64.25,9.65 64.45,9.45 64.45,0
VCC (plane layer: these items are gaps in the copper):
  lines w0.3: 36.7,15.85 36.7,21.2 46.15,30.65 46.15,32.75 46.3,32.9 49.7,32.9 49.9,33.1 49.9,34.4 ; 41.575,26.075 42.9,24.75 42.9,21 46,17.9 49.8,17.9 ; 49.8,0 49.8,17.9 ; 49.9,28.4 55.8,40.35 64.05,40.35 64.45,40.75 64.45,49.95 ; 49.9,28.5 49.9,50 ; 64.45,0 64.45,9.399 64.19,9.658 55.85,9.658 49.8,21.806 49.8,17.9 ; 39.4,12.75 39.4,15.65 39.65,15.9 42.55,15.9 42.8,15.65 42.8,12.75 42.55,12.5 39.65,12.5 39.4,12.75
  lines w0.5: 7.5,33.7 18.45,33.7 19.5,32.65 ; 30.2,50 30.2,43.35 19.5,32.65 ; 32.4,15.7 32.4,12.8 35.5,9.7 35.5,8.9 34.9,8.3 24.1,8.3 20.4,4.6 15.2,4.6 13.3,6.5 13.3,13.1 12.7,13.7 12.7,20 15.1,22.4 15.1,22.9 14.4,23.6 9.3,23.6 ; 36.7,15.7 24.8,15.7 21.422,12.322 21.422,8.022 20,6.6 16.5,6.6 16.1,7 16.1,14.5 15.1,15.5 15.1,18 19.5,22.4 19.5,32.65 ; 36.7,15.85 37.55,15 37.55,10.9 39.25,9.2 39.25,0 ; 9.3,23.6 5.9,27 5.9,28.925 7.5,30.525 7.5,33.843 6.843,34.5 5.3,34.5 4.6,33.8 4.6,32.3 3.2,30.9 3.2,26.8 5.9,24.1 5.9,20.975 6.575,20.3 8.2,20.3 9.3,21.4 9.3,23.6

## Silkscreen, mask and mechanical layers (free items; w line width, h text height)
Bottom Overlay:
  lines w0.2: 3,25 5,25 ; 4,24 4,26
Top Solder:
  drawing of 1007 lines, arcs and shapes, not listed
  text "E" at 9,45.9 h5
  text "www.bluetechnix.com" at 13.4,35.2 h1.2
  text ".prj_vers" at 0.8,23.05 h0.9 r270
  text "IN-" at 11.025,7.1 h0.6 r90
  text "FB" at 3.975,6.175 h0.6 r90
  text "IN+" at 15.5,4.3 h0.6
  text "LDK" at 29.7,2.9 h0.6
Bottom Solder:
  rectangle: 38.05,0 80,50.1
Boardoutline:
  the board outline again, w0.3
Case:
  lines w0.2: 83.8,92.5 82.3,92.5 82.3,95.5 83.8,95.5
TopDimHUM:
  circle w0.1: c2.75,47.3 r1.2
  lines w0.2: 26.422,104.609 48,89.5 70.716,105.406 ; 36.251,103.93 65,83.8 93.95,104.071
BotDimHUM:
  circle w0.01: c39.55,47.1 r2.5
  circle w0.01: c39.55,47.1 r1.2
  lines w0.2: 16,0.1 16,49.8
  text "1" at 4.5,28.4 h2
  text "2" at 10.2,28.4 h2
  text "19" at 4.1,20.7 h2
  text "20" at 11.1,20.5 h2
  text "Solder Mask Spared for Cooling" at 65,9.5 h3
Windows:
  lines w0.2: 60.8,92.5 82.1,92.5 82.1,94.5 60.8,94.5
Mechanical 15:
  lines w0.2: 58.185,90.053 cw(c65,66) 71.908,90.027
  lines w0.3: 4.5,66 4.5,78 ; 4.5,70 6.5,70 6.5,74 8.5,74 ; 4.5,80 4.5,86.975 ; 4.5,82 6.5,82 6.5,86 8.5,86 ; 8.5,66 8.5,78 ; 8.5,80 8.5,86.975 ; 46.25,89 46.25,90.5 49.75,90.5 49.75,89 ; 48,85.5 48,86.5 ; 48,87.5 48,90 ; 48,91 48,92 ; 48,93 48,95.5 ; 48,96.5 48,97.5 ; 53,87 53,89 ; 54,87 0,87 0,89 80,89 80,87 76,87 ; 55,66 55,71 75,71 75,66 ; 59.098,71 59.098,77 65,77 70.902,77 70.902,71 ; 60,77 60,83.5 ; 65,65.5 65,66.5 ; 65,67.5 65,70 ; 65,71 65,72 ; 65,73 65,75.5 ; 65,76.5 65,77.5 ; 65,78.5 65,81 ; 65,82 65,83 ; 65,84 65,86.5 ; 65,87.5 65,88.5 ; 65,89.5 65,92 ; 65,93 65,94 ; 65,95 65,97.5 ; 70,77 70,83.5 ; 0,64 80,64 80,66 0,66 0,64 ; 0.886,78 0.886,80 12,80 12,78 0.886,78 ; 54,83.5 76,83.5 76,90 54,90 54,83.5
  text "IlluminationBoard" at 12,85 h2
  text "SensorBoard" at 13.5,66.5 h2

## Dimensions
80,66 to 83.8,95.5 on TopDimHUM
80,66 to 83.8,92.5 on TopDimHUM
65,83.8 to 93.95,104.071 on TopDimHUM
0,89 to 48,97.5 on TopDimHUM
80,66 to 80,87 on TopDimHUM
65,91 to 80,66 on TopDimHUM
54,90 to 76,90 on TopDimHUM
48,97.5 to 65,97.5 on TopDimHUM
48,89.5 to 70.716,105.406 on TopDimHUM
0,0 to 39.55,2.9 on TopDimHUM
0,0 to 2.75,2.7 on TopDimHUM
0,50 to 0,0 on TopDimHUM
0,0 to 80,0 on TopDimHUM
2.75,47.3 to 5.3,45.1 on TopDimHUM
65,38 to 80,50 on TopDimHUM
0,50 to 39.55,47.1 on TopDimHUM
2.75,47.3 to 0,50 on TopDimHUM
2.75,2.7 to 2.75,47.3 on TopDimHUM
0,0 to 39.55,2.9 on TopDimHUM
39.55,47.1 to 80,50 on TopDimHUM
80,0 to 77.25,2.7 on TopDimHUM
77.25,2.7 to 80,0 on TopDimHUM
0,0 to 2.75,2.7 on TopDimHUM
80,0 to 80,12 on TopDimHUM
77.25,47.3 to 80,50 on TopDimHUM
0,0 to 7.85,42.55 on TopDimProd
0,0 to 58.3,48.2 on TopDimProd
0,0 to 26.6,6.4 on TopDimProd
80,0 to 0,0 on TopDimProd
80,0 to 80,50 on TopDimProd
0,50 to 58.8,48.7 on TopDimProd
0,50 to 8.35,43.05 on TopDimProd
0,50 to 27.1,6.9 on TopDimProd
0,0 to 24.15,1.35 on BotDimProd
0,0 to 58.7,47.6 on BotDimProd
0,0 to 1.8,18.2 on BotDimProd
0,50 to 80,50 on BotDimProd
0,0 to 1.3,18.7 on BotDimProd
0,0 to 23.65,1.85 on BotDimProd
0,0 to 58.2,48.1 on BotDimProd
80,0 to 80,50 on BotDimProd
0,50 to 4,26 on BotDimHUM
0,0 to 3,25 on BotDimHUM
0,50 to 79.3,36.8 on BotDimHUM
0,0 to 0,50 on BotDimHUM
39.55,47.1 to 42,43.7 on BotDimHUM
39.55,47.1 to 36.5,43.1 on BotDimHUM
79.3,13.2 to 38.05,0 on BotDimHUM
80,12 to 80,38 on TopDimHUM
52,25 to 65,38 on TopDimHUM
0,50 to 48,31.75 on TopDimHUM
